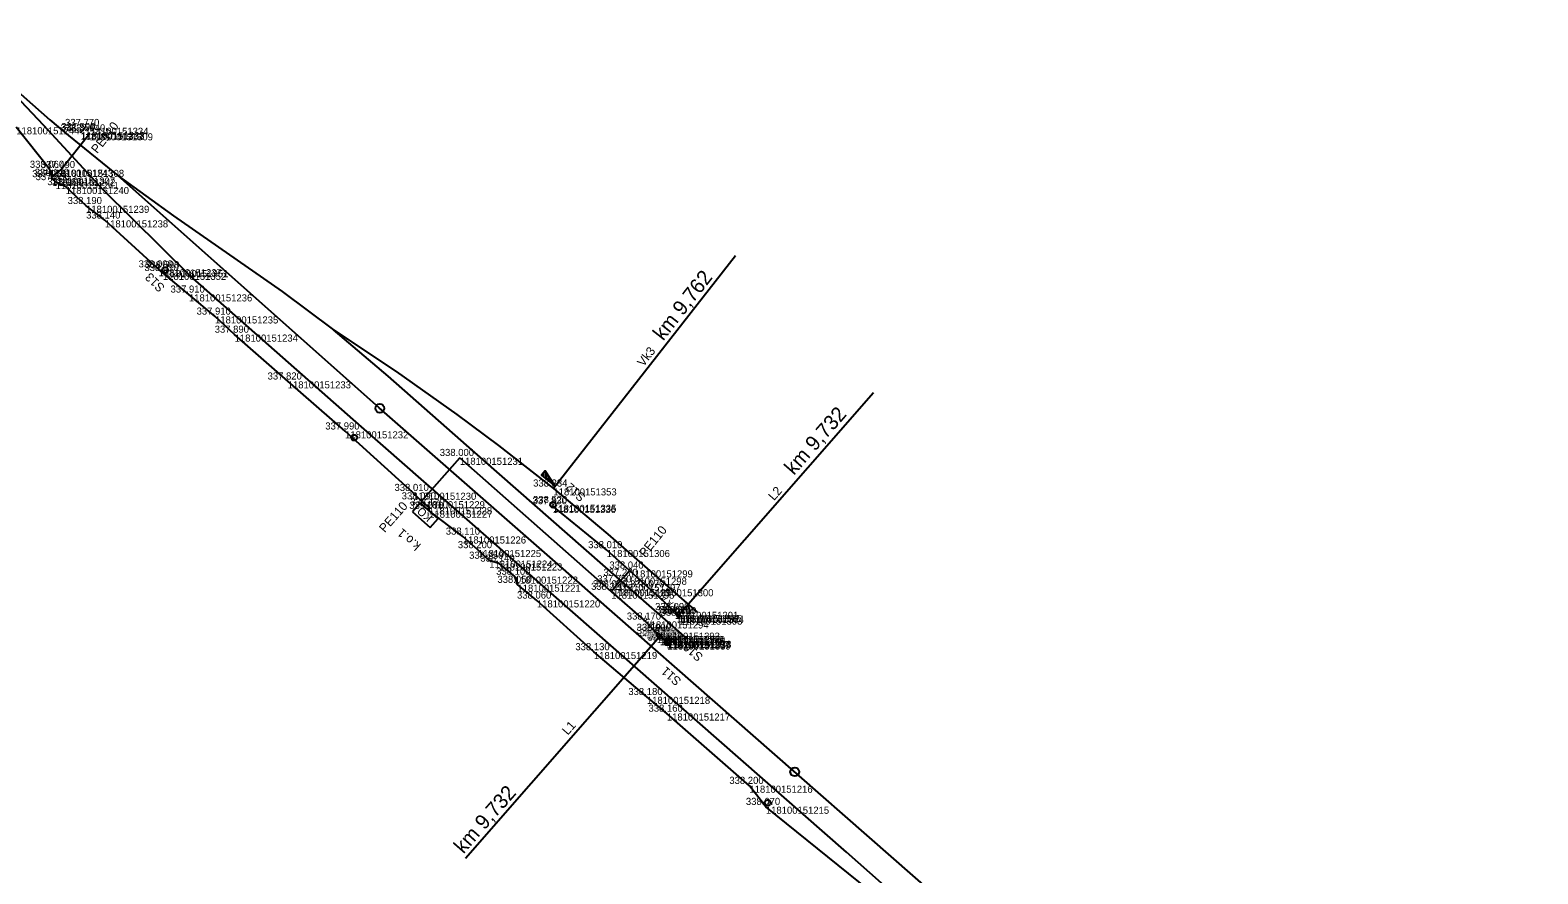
# Model space of a CAD drawing. Extents: x -732194 to -724760, y -944826 to -941477.
# Drawn here: x -726304.2 to -726048.9, y -942054.3 to -941911.5 of the extents above; entities that cross this region are included whole.
import ezdxf

# ---------------------------------------------------------------- set-up
doc = ezdxf.new("R2010")
doc.units = 0
for name, color, linetype in [('Vrstva 1', 7, 'Continuous'), ('Vrstva 28', 7, 'Continuous'), ('Vrstva 3', 7, 'Continuous'), ('Vrstva 31', 7, 'Continuous'), ('Vrstva 35', 7, 'Continuous'), ('Vrstva 36', 7, 'Continuous'), ('Vrstva 6', 7, 'Continuous'), ('Vrstva 60', 7, 'Continuous'), ('Vrstva 61', 7, 'Continuous'), ('Vrstva 7', 7, 'Continuous')]:
    doc.layers.add(name, color=color, linetype=linetype)

msp = doc.modelspace()

# ---------------------------------------------------------------- linework, layer by layer
at = {"layer": 'Vrstva 1'}
msp.add_line((-726206.35, -941996.82), (-726191.2, -942010.01), dxfattribs=at)
for points in [[(-726075.63, -942130.21), (-726101.92, -942107.27), (-726129.96, -942082.52), (-726165.94, -942050.65), (-726201.74, -942019.26), (-726248.07, -941978.65), (-726277.07, -941953.1), (-726291.76, -941938.6), (-726301.83, -941927.65), (-726309.68, -941919.38), (-726318.02, -941911.5), (-726300.8, -941926.68), (-726297.65, -941929.32), (-726289.24, -941936.18), (-726279.87, -941942.93), (-726261.51, -941955.72), (-726252.77, -941962.25), (-726242.17, -941969.3), (-726231.93, -941976.55), (-726224.85, -941981.79)], [(-726048.89, -942147.24), (-726074.43, -942124.89), (-726107.88, -942095.67), (-726138.68, -942068.63), (-726178.07, -942034.11), (-726215.25, -942001.51), (-726245.07, -941975.42), (-726289.24, -941936.18)], [(-726192.93, -942014.51), (-726227.48, -941984.21), (-726243.55, -941970.08), (-726252.77, -941962.25)], [(-726224.85, -941981.79), (-726215.56, -941989.06), (-726206.35, -941996.82)]]:
    msp.add_lwpolyline(points, dxfattribs=at)
at = {"layer": 'Vrstva 28'}
for p, q in [((-726281.31, -941952.12), (-726281.67, -941952.57)), ((-726281.35, -941952.08), (-726281.27, -941952.16)), ((-726231.41, -941983.88), (-726237.88, -941991.23)), ((-726231.41, -941983.88), (-726205.78, -942006.54)), ((-726238.11, -941991.51), (-726239.43, -941993.03)), ((-726235.07, -941994.17), (-726238.11, -941991.51)), ((-726206.55, -941999.49), (-726215.69, -941992.04)), ((-726215.65, -941991.82), (-726215.57, -941991.88)), ((-726239.43, -941993.03), (-726236.4, -941995.68)), ((-726236.4, -941995.68), (-726235.07, -941994.17)), ((-726196.3, -942015.12), (-726196.22, -942015.18)), ((-726196.09, -942014.89), (-726196.17, -942014.83))]:
    msp.add_line(p, q, dxfattribs=at)
for points in [[(-726160.36, -942058.51), (-726179.59, -942042.95), (-726182.38, -942039.39), (-726196.35, -942027.17), (-726199.74, -942024.35), (-726208.7, -942016.76), (-726218.35, -942008.02), (-726221.65, -942005.36), (-726222.12, -942003.99), (-726224.76, -942001.77), (-726226.43, -942001.28), (-726228.35, -941999.49), (-726230.9, -941997.2), (-726236.59, -941992.84), (-726236.65, -941992.25), (-726237.88, -941991.23), (-726239.33, -941989.8), (-726250.83, -941979.4), (-726260.55, -941970.94), (-726269.53, -941963.02), (-726272.85, -941959.95), (-726277.26, -941956.22), (-726281.67, -941952.57), (-726282.4, -941951.96), (-726291.5, -941943.69), (-726294.69, -941941.23), (-726298.13, -941938.04), (-726299.84, -941937.19), (-726300.42, -941936.69), (-726300.49, -941936.44), (-726300.83, -941935.1), (-726306.5, -941927.93)], [(-726295.6, -941928.89), (-726295.51, -941928.72), (-726294.83, -941928.02)], [(-726300.49, -941936.44), (-726298.95, -941935.14), (-726294.07, -941928.95)], [(-726215.61, -941991.85), (-726215.69, -941992.04)], [(-726202.67, -942002.94), (-726206.55, -941999.49)], [(-726205.47, -942006.11), (-726204.74, -942005.28), (-726203.68, -942004.18), (-726202.67, -942002.94)], [(-726202.67, -942002.94), (-726199.17, -942006.13), (-726194.97, -942009.96), (-726194.73, -942010.54), (-726194.28, -942010.93), (-726194.03, -942010.64), (-726194.35, -942010.5)], [(-726205.78, -942006.54), (-726205.47, -942006.11)], [(-726205.78, -942006.54), (-726199.99, -942011.58), (-726198.08, -942013.48), (-726198.04, -942014.03), (-726197.55, -942014.42), (-726197.16, -942014.41), (-726196.38, -942014.92)], [(-726197.16, -942014.41), (-726197.19, -942014.09), (-726197.49, -942014.04)], [(-726196.38, -942014.92), (-726196.27, -942014.97), (-726196.26, -942015.15)], [(-726196.27, -942014.97), (-726196.13, -942014.86)]]:
    msp.add_lwpolyline(points, dxfattribs=at)
for centre in [(-726281.31, -941952.12), (-726215.61, -941991.85), (-726196.26, -942015.15), (-726196.13, -942014.86)]:
    msp.add_circle(centre, 0.5, dxfattribs=at)
at = {"layer": 'Vrstva 3'}
for p, q in [((-726184.74, -941949.69), (-726215.56, -941989.06)), ((-726217.57, -941986.85), (-726217.56, -941986.84)), ((-726217.16, -941987.17), (-726217.24, -941986.42)), ((-726216.75, -941987.5), (-726216.9, -941986.16)), ((-726216.33, -941987.82), (-726216.45, -941986.85)), ((-726215.92, -941988.14), (-726216, -941987.53)), ((-726215.51, -941988.47), (-726215.54, -941988.23))]:
    msp.add_line(p, q, dxfattribs=at)
msp.add_lwpolyline([(-726215.25, -941988.67), (-726216.97, -941986.07), (-726217.57, -941986.85), (-726215.25, -941988.67)], dxfattribs=at)
msp.add_lwpolyline([(-726215.25, -941988.67), (-726216.97, -941986.07), (-726217.57, -941986.85), (-726215.25, -941988.67)], dxfattribs=at)
at = {"layer": 'Vrstva 31'}
msp.add_lwpolyline([(-726160.36, -942058.51), (-726179.59, -942042.95), (-726182.38, -942039.39), (-726196.35, -942027.17), (-726199.74, -942024.35), (-726208.7, -942016.76), (-726218.35, -942008.02), (-726221.65, -942005.36), (-726222.12, -942003.99), (-726224.76, -942001.77), (-726226.43, -942001.28), (-726228.35, -941999.49), (-726230.9, -941997.2), (-726236.59, -941992.84), (-726236.65, -941992.25), (-726237.88, -941991.23), (-726239.33, -941989.8), (-726250.83, -941979.4), (-726260.55, -941970.94), (-726269.53, -941963.02), (-726272.85, -941959.95), (-726277.26, -941956.22), (-726281.67, -941952.57), (-726282.4, -941951.96), (-726291.5, -941943.69), (-726294.69, -941941.23), (-726298.13, -941938.04), (-726299.84, -941937.19), (-726300.42, -941936.69), (-726300.49, -941936.44), (-726300.83, -941935.1), (-726306.5, -941927.93)], dxfattribs=at)
at = {"layer": 'Vrstva 35'}
for points in [[(-726298.95, -941935.14), (-726294.07, -941928.95)], [(-726237.88, -941991.23), (-726231.41, -941983.88)], [(-726205.47, -942006.11), (-726204.74, -942005.28), (-726203.68, -942004.18), (-726202.67, -942002.94)]]:
    msp.add_lwpolyline(points, dxfattribs=at)
at = {"layer": 'Vrstva 6'}
for p, q in [((-726161.39, -941972.9), (-726194.35, -942010.5)), ((-726195.84, -942009.19), (-726194.35, -942010.5)), ((-726194.68, -942010.88), (-726194.02, -942010.12)), ((-726198.98, -942012.73), (-726197.49, -942014.04)), ((-726230.45, -942051.64), (-726197.49, -942014.04)), ((-726197.82, -942014.42), (-726197.16, -942013.66))]:
    msp.add_line(p, q, dxfattribs=at)
at = {"layer": 'Vrstva 60'}
for p, q in [((-726294.83, -941928.02), (-726294.83, -941928.02)), ((-726295.6, -941928.89), (-726295.6, -941928.89)), ((-726295.51, -941928.72), (-726295.51, -941928.72)), ((-726294.07, -941928.95), (-726294.07, -941928.95)), ((-726300.83, -941935.1), (-726300.83, -941935.1)), ((-726298.95, -941935.14), (-726298.95, -941935.14)), ((-726300.49, -941936.44), (-726300.49, -941936.44)), ((-726300.42, -941936.69), (-726300.42, -941936.69)), ((-726299.84, -941937.19), (-726299.84, -941937.19)), ((-726298.13, -941938.04), (-726298.13, -941938.04)), ((-726294.69, -941941.23), (-726294.69, -941941.23)), ((-726291.5, -941943.69), (-726291.5, -941943.69)), ((-726282.4, -941951.96), (-726282.4, -941951.96)), ((-726281.67, -941952.57), (-726281.67, -941952.57)), ((-726281.31, -941952.12), (-726281.31, -941952.12)), ((-726277.26, -941956.22), (-726277.26, -941956.22)), ((-726272.85, -941959.95), (-726272.85, -941959.95)), ((-726269.53, -941963.02), (-726269.53, -941963.02)), ((-726260.55, -941970.94), (-726260.55, -941970.94)), ((-726250.83, -941979.4), (-726250.83, -941979.4)), ((-726231.41, -941983.88), (-726231.41, -941983.88)), ((-726239.33, -941989.8), (-726239.33, -941989.8)), ((-726215.56, -941989.06), (-726215.56, -941989.06)), ((-726237.88, -941991.23), (-726237.88, -941991.23)), ((-726236.65, -941992.25), (-726236.65, -941992.25)), ((-726215.69, -941992.04), (-726215.69, -941992.04)), ((-726215.61, -941991.85), (-726215.61, -941991.85)), ((-726236.59, -941992.84), (-726236.59, -941992.84)), ((-726230.9, -941997.2), (-726230.9, -941997.2)), ((-726228.35, -941999.49), (-726228.35, -941999.49)), ((-726206.55, -941999.49), (-726206.55, -941999.49)), ((-726226.43, -942001.28), (-726226.43, -942001.28)), ((-726224.76, -942001.77), (-726224.76, -942001.77)), ((-726222.12, -942003.99), (-726222.12, -942003.99)), ((-726203.68, -942004.18), (-726203.68, -942004.18)), ((-726202.67, -942002.94), (-726202.67, -942002.94)), ((-726221.65, -942005.36), (-726221.65, -942005.36)), ((-726205.78, -942006.54), (-726205.78, -942006.54)), ((-726205.47, -942006.11), (-726205.47, -942006.11)), ((-726204.74, -942005.28), (-726204.74, -942005.28)), ((-726199.17, -942006.13), (-726199.17, -942006.13)), ((-726218.35, -942008.02), (-726218.35, -942008.02)), ((-726194.97, -942009.96), (-726194.97, -942009.96)), ((-726199.99, -942011.58), (-726199.99, -942011.58)), ((-726194.73, -942010.54), (-726194.73, -942010.54)), ((-726194.35, -942010.5), (-726194.35, -942010.5)), ((-726194.28, -942010.93), (-726194.28, -942010.93)), ((-726194.03, -942010.64), (-726194.03, -942010.64)), ((-726198.08, -942013.48), (-726198.08, -942013.48)), ((-726198.04, -942014.03), (-726198.04, -942014.03)), ((-726197.55, -942014.42), (-726197.55, -942014.42)), ((-726197.49, -942014.04), (-726197.49, -942014.04)), ((-726197.19, -942014.09), (-726197.19, -942014.09)), ((-726197.16, -942014.41), (-726197.16, -942014.41)), ((-726196.38, -942014.92), (-726196.38, -942014.92)), ((-726196.27, -942014.97), (-726196.27, -942014.97)), ((-726196.26, -942015.15), (-726196.26, -942015.15)), ((-726196.13, -942014.86), (-726196.13, -942014.86)), ((-726208.7, -942016.76), (-726208.7, -942016.76)), ((-726199.74, -942024.35), (-726199.74, -942024.35)), ((-726196.35, -942027.17), (-726196.35, -942027.17)), ((-726182.38, -942039.39), (-726182.38, -942039.39)), ((-726179.59, -942042.95), (-726179.59, -942042.95))]:
    msp.add_line(p, q, dxfattribs=at)
at = {"layer": 'Vrstva 7'}
for p, q in [((-726249.32, -941980.44), (-726249.25, -941980.51)), ((-726179.33, -942042.27), (-726179.26, -942042.34))]:
    msp.add_line(p, q, dxfattribs=at)
for centre, radius in [((-726244.95, -941975.52), 0.75), ((-726249.29, -941980.48), 0.5), ((-726174.7, -942037.06), 0.75), ((-726179.3, -942042.3), 0.5)]:
    msp.add_circle(centre, radius, dxfattribs=at)

# ---------------------------------------------------------------- texts
at = {"layer": 'Vrstva 28'}
for s, height, rotation, p in [('S13', 1.5, 135.3945, (-726281.24, -941954.94)), ('S12', 1.5, 138.7578, (-726209.98, -941990.35)), ('KO', 1.344, 138.7644, (-726235.94, -941993.84)), ('k.o.1', 1.5, 138.7644, (-726237.89, -941998.6)), ('S10', 1.5, 138.7578, (-726190.1, -942017.39)), ('S11', 1.5, 138.7533, (-726193.79, -942021.49))]:
    msp.add_text(s, height=height, rotation=rotation, dxfattribs=at).set_placement(p)
at = {"layer": 'Vrstva 3'}
for s, height, p in [('km 9,762', 2.5, (-726196.97, -941964.21)), ('Vk3', 1.5, (-726200.32, -941968.57))]:
    msp.add_text(s, height=height, rotation=51.9415, dxfattribs=at).set_placement(p)
at = {"layer": 'Vrstva 36'}
for rotation, p in [(51.7489, (-726292.79, -941932.48)), (48.6434, (-726244.1, -941996.66)), (50.8366, (-726200.05, -942000.83))]:
    msp.add_text('PE110', height=1.5, rotation=rotation, dxfattribs=at).set_placement(p)
at = {"layer": 'Vrstva 6'}
for s, height, rotation, p in [('km 9,732', 2.5, 48.7578, (-726174.84, -941986.96)), ('L2', 1.5, 48.7578, (-726178.21, -941991.24)), ('  A A A ', 1, 138.7578, (-726193.69, -942009.75)), ('  A A A ', 1, 138.7557, (-726196.83, -942013.29)), ('L1', 1.5, 48.7557, (-726213.13, -942030.93)), ('km 9,732', 2.5, 48.7557, (-726230.78, -942051.06))]:
    msp.add_text(s, height=height, rotation=rotation, dxfattribs=at).set_placement(p)
at = {"layer": 'Vrstva 60'}
for s, p in [('118100151244', (-726306.5, -941929.13)), ('118100151334', (-726294.83, -941929.22)), ('118100151332', (-726295.6, -941930.09)), ('118100151333', (-726295.51, -941929.92)), ('118100151309', (-726294.07, -941930.15)), ('118100151243', (-726300.83, -941936.3)), ('118100151308', (-726298.95, -941936.34)), ('118100151307', (-726300.49, -941937.64)), ('118100151242', (-726300.42, -941937.89)), ('118100151241', (-726299.84, -941938.39)), ('118100151240', (-726298.13, -941939.24)), ('118100151239', (-726294.69, -941942.43)), ('118100151238', (-726291.5, -941944.89)), ('118100151237', (-726282.4, -941953.16)), ('118100151352', (-726281.67, -941953.77)), ('118100151351', (-726281.31, -941953.32)), ('118100151236', (-726277.26, -941957.42)), ('118100151235', (-726272.85, -941961.15)), ('118100151234', (-726269.53, -941964.22)), ('118100151233', (-726260.55, -941972.14)), ('118100151232', (-726250.83, -941980.6)), ('118100151231', (-726231.41, -941985.08)), ('118100151230', (-726239.33, -941991)), ('118100151353', (-726215.56, -941990.26)), ('118100151229', (-726237.88, -941992.43)), ('118100151228', (-726236.65, -941993.45)), ('118100151336', (-726215.69, -941993.24)), ('118100151335', (-726215.61, -941993.05)), ('118100151227', (-726236.59, -941994.04)), ('118100151226', (-726230.9, -941998.4)), ('118100151225', (-726228.35, -942000.69)), ('118100151306', (-726206.55, -942000.69)), ('118100151224', (-726226.43, -942002.48)), ('118100151223', (-726224.76, -942002.97)), ('118100151222', (-726222.12, -942005.19)), ('118100151297', (-726204.74, -942006.48)), ('118100151298', (-726203.68, -942005.38)), ('118100151299', (-726202.67, -942004.14)), ('118100151221', (-726221.65, -942006.56)), ('118100151295', (-726205.78, -942007.74)), ('118100151296', (-726205.47, -942007.31)), ('118100151300', (-726199.17, -942007.33)), ('118100151220', (-726218.35, -942009.22)), ('118100151301', (-726194.97, -942011.16)), ('118100151294', (-726199.99, -942012.78)), ('118100151302', (-726194.73, -942011.74)), ('118100151305', (-726194.35, -942011.7)), ('118100151303', (-726194.28, -942012.13)), ('118100151304', (-726194.03, -942011.84)), ('118100151293', (-726198.08, -942014.68)), ('118100151292', (-726198.04, -942015.23)), ('118100151291', (-726197.55, -942015.62)), ('118100151290', (-726197.49, -942015.24)), ('118100151289', (-726197.19, -942015.29)), ('118100151288', (-726197.16, -942015.61)), ('118100151287', (-726196.38, -942016.12)), ('118100151337', (-726196.27, -942016.17)), ('118100151339', (-726196.26, -942016.35)), ('118100151338', (-726196.13, -942016.06)), ('118100151219', (-726208.7, -942017.96)), ('118100151218', (-726199.74, -942025.55)), ('118100151217', (-726196.35, -942028.37)), ('118100151216', (-726182.38, -942040.59)), ('118100151215', (-726179.59, -942044.15))]:
    msp.add_text(s, height=1.2, dxfattribs=at).set_placement(p)
at = {"layer": 'Vrstva 61'}
for s, p in [('338.350', (-726299, -941928.59)), ('337.590', (-726298.89, -941928.42)), ('337.770', (-726298.24, -941927.72)), ('337.140', (-726297.24, -941928.65)), ('338.060', (-726304.2, -941934.8)), ('337.490', (-726302.35, -941934.84)), ('337.950', (-726303.8, -941936.39)), ('338.110', (-726303.37, -941936.14)), ('337.950', (-726303.22, -941936.89)), ('338.160', (-726301.24, -941937.74)), ('338.190', (-726297.8, -941940.93)), ('338.140', (-726294.67, -941943.39)), ('338.000', (-726285.79, -941951.66)), ('338.010', (-726284.8, -941952.27)), ('338.590', (-726284.68, -941951.82)), ('337.910', (-726280.38, -941955.92)), ('337.910', (-726275.97, -941959.65)), ('337.890', (-726272.91, -941962.72)), ('337.820', (-726263.95, -941970.64)), ('337.990', (-726254.18, -941979.1)), ('338.000', (-726234.8, -941983.58)), ('338.010', (-726242.46, -941989.5)), ('338.090', (-726241.25, -941990.93)), ('338.334', (-726218.99, -941988.76)), ('339.070', (-726239.96, -941992.54)), ('338.120', (-726239.79, -941991.95)), ('337.830', (-726219.09, -941991.74)), ('338.520', (-726219.01, -941991.55)), ('338.110', (-726233.78, -941996.9)), ('338.200', (-726231.74, -941999.19)), ('338.250', (-726229.83, -942000.98)), ('338.010', (-726209.68, -941999.19)), ('338.140', (-726227.93, -942001.47)), ('338.100', (-726225.25, -942003.69)), ('337.270', (-726207.09, -942003.88)), ('338.040', (-726206.09, -942002.64)), ('338.050', (-726225.04, -942005.06)), ('338.220', (-726209.18, -942006.24)), ('338.020', (-726208.86, -942005.81)), ('337.250', (-726208.14, -942004.98)), ('338.070', (-726202.57, -942005.83)), ('338.060', (-726221.72, -942007.72)), ('338.170', (-726203.13, -942011.28)), ('338.090', (-726198.34, -942009.66)), ('338.020', (-726198.12, -942010.24)), ('338.660', (-726197.69, -942010.2)), ('338.010', (-726197.41, -942010.63)), ('338.010', (-726197.16, -942010.34)), ('338.000', (-726201.47, -942013.18)), ('338.040', (-726201.46, -942013.73)), ('338.040', (-726200.97, -942014.12)), ('338.710', (-726200.63, -942013.74)), ('338.030', (-726200.58, -942013.79)), ('338.010', (-726200.29, -942014.11)), ('338.130', (-726211.84, -942016.46)), ('338.020', (-726199.77, -942014.62)), ('337.940', (-726199.67, -942014.67)), ('338.630', (-726199.63, -942014.85)), ('338.640', (-726199.53, -942014.56)), ('338.180', (-726202.88, -942024.05)), ('338.160', (-726199.46, -942026.87)), ('338.200', (-726185.77, -942039.09)), ('338.670', (-726182.97, -942042.65))]:
    msp.add_text(s, height=1.2, dxfattribs=at).set_placement(p)

doc.saveas('drawing.dxf')
